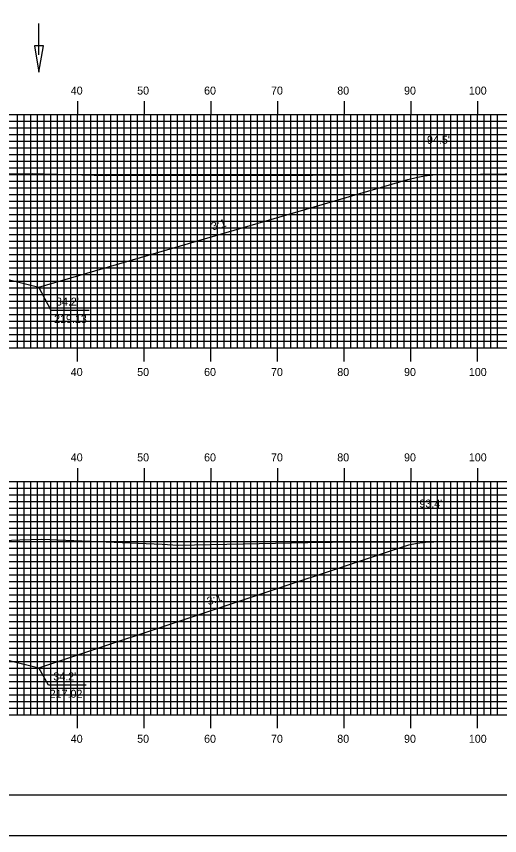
# Model space of a CAD drawing. Extents: x 1802323 to 1802666, y 442591 to 442811.
# Drawn here: x 1802519.4 to 1802591.9, y 442590.5 to 442713.4 of the extents above; entities that cross this region are included whole.
import ezdxf

# ---------------------------------------------------------------- set-up
doc = ezdxf.new("R2010")
doc.units = 0
for name, color, linetype in [('ANNOTATION', 7, 'Continuous'), ('BORDER', 7, 'Continuous'), ('D_Drainage_Ditch_Line', 7, 'Continuous'), ('D_Roadway_Centerline', 7, 'Continuous'), ('D_Roadway_SlopeLines', 7, 'Continuous'), ('D_Text_Standard', 7, 'Continuous'), ('H_V ANNOTATION', 7, 'Continuous'), ('MAJOR', 7, 'Continuous'), ('MINOR', 7, 'Continuous'), ('PLOT BOUNDARY', 7, 'Continuous'), ('S_Roadway_Centerline', 7, 'Continuous')]:
    doc.layers.add(name, color=color, linetype=linetype)

msp = doc.modelspace()

# ---------------------------------------------------------------- linework, layer by layer
at = {"layer": 'ANNOTATION'}
for points in [[(1802530.31, 442669.3), (1802524.62, 442669.3), (1802522.78, 442672.8)], [(1802529.9, 442613.09), (1802524.21, 442613.09), (1802522.78, 442615.69)]]:
    msp.add_lwpolyline(points, dxfattribs=at)
at = {"layer": 'BORDER'}
msp.add_lwpolyline([(1802339, 442596.67), (1802659, 442596.67), (1802659, 442806.67), (1802339, 442806.67)], close=True, dxfattribs=at)
at = {"layer": 'D_Drainage_Ditch_Line'}
msp.add_line((1802522.8, 442707.65), (1802522.8, 442712.35), dxfattribs=at)
msp.add_lwpolyline([(1802523.46, 442708.96), (1802522.15, 442708.96), (1802522.8, 442705.03)], close=True, dxfattribs=at)
at = {"layer": 'D_Roadway_Centerline'}
for points in [[(1802396.07, 442689.17), (1802397.32, 442689.09), (1802398.57, 442688.93), (1802399.82, 442688.68), (1802401.07, 442688.36), (1802454.43, 442672.8), (1802458.43, 442673.8), (1802468.6, 442676.34), (1802476.6, 442676.66), (1802488.6, 442676.9), (1802500.6, 442676.66), (1802508.6, 442676.34), (1802518.78, 442673.8), (1802522.78, 442672.8), (1802578.12, 442688.94), (1802579.37, 442689.26), (1802580.62, 442689.49), (1802581.87, 442689.62), (1802583.12, 442689.67)], [(1802397.15, 442633.97), (1802398.4, 442633.91), (1802399.65, 442633.74), (1802400.9, 442633.48), (1802402.15, 442633.11), (1802454.43, 442615.69), (1802458.43, 442616.69), (1802468.6, 442619.23), (1802476.6, 442619.55), (1802488.6, 442619.79), (1802500.6, 442619.55), (1802508.6, 442619.23), (1802518.78, 442616.69), (1802522.78, 442615.69), (1802577.02, 442633.77), (1802578.27, 442634.13), (1802579.52, 442634.39), (1802580.77, 442634.56), (1802582.02, 442634.61)]]:
    msp.add_lwpolyline(points, dxfattribs=at)
at = {"layer": 'D_Roadway_SlopeLines'}
for points in [[(1802522.78, 442672.8), (1802578.12, 442688.94), (1802579.37, 442689.26), (1802580.62, 442689.49), (1802581.87, 442689.62), (1802583.12, 442689.67)], [(1802508.6, 442676.34), (1802522.78, 442672.8)], [(1802522.78, 442615.69), (1802577.02, 442633.77), (1802578.27, 442634.13), (1802579.52, 442634.39), (1802580.77, 442634.56), (1802582.02, 442634.61)], [(1802508.6, 442619.23), (1802522.78, 442615.69)]]:
    msp.add_lwpolyline(points, dxfattribs=at)
at = {"layer": 'MAJOR'}
for p, q in [((1802528.6, 442700.67), (1802528.6, 442698.67)), ((1802538.6, 442700.67), (1802538.6, 442698.67)), ((1802548.6, 442700.67), (1802548.6, 442698.67)), ((1802558.6, 442700.67), (1802558.6, 442698.67)), ((1802568.6, 442700.67), (1802568.6, 442698.67)), ((1802578.6, 442700.67), (1802578.6, 442698.67)), ((1802588.6, 442700.67), (1802588.6, 442698.67)), ((1802348.6, 442698.67), (1802628.6, 442698.67)), ((1802348.6, 442698.67), (1802628.6, 442698.67)), ((1802528.6, 442663.67), (1802528.6, 442698.67)), ((1802538.6, 442663.67), (1802538.6, 442698.67)), ((1802548.6, 442663.67), (1802548.6, 442698.67)), ((1802558.6, 442663.67), (1802558.6, 442698.67)), ((1802568.6, 442663.67), (1802568.6, 442698.67)), ((1802578.6, 442663.67), (1802578.6, 442698.67)), ((1802588.6, 442663.67), (1802588.6, 442698.67)), ((1802348.6, 442693.67), (1802628.6, 442693.67)), ((1802348.6, 442688.67), (1802628.6, 442688.67)), ((1802348.6, 442683.67), (1802628.6, 442683.67)), ((1802348.6, 442678.67), (1802628.6, 442678.67)), ((1802348.6, 442673.67), (1802628.6, 442673.67)), ((1802348.6, 442668.67), (1802628.6, 442668.67)), ((1802348.6, 442663.67), (1802628.6, 442663.67)), ((1802348.6, 442663.67), (1802628.6, 442663.67)), ((1802528.6, 442661.66), (1802528.6, 442663.67)), ((1802538.6, 442661.66), (1802538.6, 442663.67)), ((1802548.6, 442661.66), (1802548.6, 442663.67)), ((1802558.6, 442661.66), (1802558.6, 442663.67)), ((1802568.6, 442661.66), (1802568.6, 442663.67)), ((1802578.6, 442661.66), (1802578.6, 442663.67)), ((1802588.6, 442661.66), (1802588.6, 442663.67)), ((1802528.6, 442645.67), (1802528.6, 442643.67)), ((1802538.6, 442645.67), (1802538.6, 442643.67)), ((1802548.6, 442645.67), (1802548.6, 442643.67)), ((1802558.6, 442645.67), (1802558.6, 442643.67)), ((1802568.6, 442645.67), (1802568.6, 442643.67)), ((1802578.6, 442645.67), (1802578.6, 442643.67)), ((1802588.6, 442645.67), (1802588.6, 442643.67)), ((1802348.6, 442643.67), (1802628.6, 442643.67)), ((1802348.6, 442643.67), (1802628.6, 442643.67)), ((1802528.6, 442608.67), (1802528.6, 442643.67)), ((1802538.6, 442608.67), (1802538.6, 442643.67)), ((1802548.6, 442608.67), (1802548.6, 442643.67)), ((1802558.6, 442608.67), (1802558.6, 442643.67)), ((1802568.6, 442608.67), (1802568.6, 442643.67)), ((1802578.6, 442608.67), (1802578.6, 442643.67)), ((1802588.6, 442608.67), (1802588.6, 442643.67)), ((1802348.6, 442638.67), (1802628.6, 442638.67)), ((1802348.6, 442633.67), (1802628.6, 442633.67)), ((1802348.6, 442628.67), (1802628.6, 442628.67)), ((1802348.6, 442623.67), (1802628.6, 442623.67)), ((1802348.6, 442618.67), (1802628.6, 442618.67)), ((1802348.6, 442613.67), (1802628.6, 442613.67)), ((1802348.6, 442608.67), (1802628.6, 442608.67)), ((1802348.6, 442608.67), (1802628.6, 442608.67)), ((1802528.6, 442606.66), (1802528.6, 442608.67)), ((1802538.6, 442606.66), (1802538.6, 442608.67)), ((1802548.6, 442606.66), (1802548.6, 442608.67)), ((1802558.6, 442606.66), (1802558.6, 442608.67)), ((1802568.6, 442606.66), (1802568.6, 442608.67)), ((1802578.6, 442606.66), (1802578.6, 442608.67)), ((1802588.6, 442606.66), (1802588.6, 442608.67))]:
    msp.add_line(p, q, dxfattribs=at)
at = {"layer": 'MINOR'}
for p, q in [((1802519.6, 442663.67), (1802519.6, 442698.67)), ((1802520.6, 442663.67), (1802520.6, 442698.67)), ((1802521.6, 442663.67), (1802521.6, 442698.67)), ((1802522.6, 442663.67), (1802522.6, 442698.67)), ((1802523.6, 442663.67), (1802523.6, 442698.67)), ((1802524.6, 442663.67), (1802524.6, 442698.67)), ((1802525.6, 442663.67), (1802525.6, 442698.67)), ((1802526.6, 442663.67), (1802526.6, 442698.67)), ((1802527.6, 442663.67), (1802527.6, 442698.67)), ((1802529.6, 442663.67), (1802529.6, 442698.67)), ((1802530.6, 442663.67), (1802530.6, 442698.67)), ((1802531.6, 442663.67), (1802531.6, 442698.67)), ((1802532.6, 442663.67), (1802532.6, 442698.67)), ((1802533.6, 442663.67), (1802533.6, 442698.67)), ((1802534.6, 442663.67), (1802534.6, 442698.67)), ((1802535.6, 442663.67), (1802535.6, 442698.67)), ((1802536.6, 442663.67), (1802536.6, 442698.67)), ((1802537.6, 442663.67), (1802537.6, 442698.67)), ((1802539.6, 442663.67), (1802539.6, 442698.67)), ((1802540.6, 442663.67), (1802540.6, 442698.67)), ((1802541.6, 442663.67), (1802541.6, 442698.67)), ((1802542.6, 442663.67), (1802542.6, 442698.67)), ((1802543.6, 442663.67), (1802543.6, 442698.67)), ((1802544.6, 442663.67), (1802544.6, 442698.67)), ((1802545.6, 442663.67), (1802545.6, 442698.67)), ((1802546.6, 442663.67), (1802546.6, 442698.67)), ((1802547.6, 442663.67), (1802547.6, 442698.67)), ((1802549.6, 442663.67), (1802549.6, 442698.67)), ((1802550.6, 442663.67), (1802550.6, 442698.67)), ((1802551.6, 442663.67), (1802551.6, 442698.67)), ((1802552.6, 442663.67), (1802552.6, 442698.67)), ((1802553.6, 442663.67), (1802553.6, 442698.67)), ((1802554.6, 442663.67), (1802554.6, 442698.67)), ((1802555.6, 442663.67), (1802555.6, 442698.67)), ((1802556.6, 442663.67), (1802556.6, 442698.67)), ((1802557.6, 442663.67), (1802557.6, 442698.67)), ((1802559.6, 442663.67), (1802559.6, 442698.67)), ((1802560.6, 442663.67), (1802560.6, 442698.67)), ((1802561.6, 442663.67), (1802561.6, 442698.67)), ((1802562.6, 442663.67), (1802562.6, 442698.67)), ((1802563.6, 442663.67), (1802563.6, 442698.67)), ((1802564.6, 442663.67), (1802564.6, 442698.67)), ((1802565.6, 442663.67), (1802565.6, 442698.67)), ((1802566.6, 442663.67), (1802566.6, 442698.67)), ((1802567.6, 442663.67), (1802567.6, 442698.67)), ((1802569.6, 442663.67), (1802569.6, 442698.67)), ((1802570.6, 442663.67), (1802570.6, 442698.67)), ((1802571.6, 442663.67), (1802571.6, 442698.67)), ((1802572.6, 442663.67), (1802572.6, 442698.67)), ((1802573.6, 442663.67), (1802573.6, 442698.67)), ((1802574.6, 442663.67), (1802574.6, 442698.67)), ((1802575.6, 442663.67), (1802575.6, 442698.67)), ((1802576.6, 442663.67), (1802576.6, 442698.67)), ((1802577.6, 442663.67), (1802577.6, 442698.67)), ((1802579.6, 442663.67), (1802579.6, 442698.67)), ((1802580.6, 442663.67), (1802580.6, 442698.67)), ((1802581.6, 442663.67), (1802581.6, 442698.67)), ((1802582.6, 442663.67), (1802582.6, 442698.67)), ((1802583.6, 442663.67), (1802583.6, 442698.67)), ((1802584.6, 442663.67), (1802584.6, 442698.67)), ((1802585.6, 442663.67), (1802585.6, 442698.67)), ((1802586.6, 442663.67), (1802586.6, 442698.67)), ((1802587.6, 442663.67), (1802587.6, 442698.67)), ((1802589.6, 442663.67), (1802589.6, 442698.67)), ((1802590.6, 442663.67), (1802590.6, 442698.67)), ((1802591.6, 442663.67), (1802591.6, 442698.67)), ((1802348.6, 442697.67), (1802628.6, 442697.67)), ((1802348.6, 442696.67), (1802628.6, 442696.67)), ((1802348.6, 442695.67), (1802628.6, 442695.67)), ((1802348.6, 442694.67), (1802628.6, 442694.67)), ((1802348.6, 442692.67), (1802628.6, 442692.67)), ((1802348.6, 442691.67), (1802628.6, 442691.67)), ((1802348.6, 442690.67), (1802628.6, 442690.67)), ((1802348.6, 442689.67), (1802628.6, 442689.67)), ((1802348.6, 442687.67), (1802628.6, 442687.67)), ((1802348.6, 442686.67), (1802628.6, 442686.67)), ((1802348.6, 442685.67), (1802628.6, 442685.67)), ((1802348.6, 442684.67), (1802628.6, 442684.67)), ((1802348.6, 442682.67), (1802628.6, 442682.67)), ((1802348.6, 442681.67), (1802628.6, 442681.67)), ((1802348.6, 442680.67), (1802628.6, 442680.67)), ((1802348.6, 442679.67), (1802628.6, 442679.67)), ((1802348.6, 442677.67), (1802628.6, 442677.67)), ((1802348.6, 442676.67), (1802628.6, 442676.67)), ((1802348.6, 442675.67), (1802628.6, 442675.67)), ((1802348.6, 442674.67), (1802628.6, 442674.67)), ((1802348.6, 442672.67), (1802628.6, 442672.67)), ((1802348.6, 442671.67), (1802628.6, 442671.67)), ((1802348.6, 442670.67), (1802628.6, 442670.67)), ((1802348.6, 442669.67), (1802628.6, 442669.67)), ((1802348.6, 442667.67), (1802628.6, 442667.67)), ((1802348.6, 442666.67), (1802628.6, 442666.67)), ((1802348.6, 442665.67), (1802628.6, 442665.67)), ((1802348.6, 442664.67), (1802628.6, 442664.67)), ((1802519.6, 442608.67), (1802519.6, 442643.67)), ((1802520.6, 442608.67), (1802520.6, 442643.67)), ((1802521.6, 442608.67), (1802521.6, 442643.67)), ((1802522.6, 442608.67), (1802522.6, 442643.67)), ((1802523.6, 442608.67), (1802523.6, 442643.67)), ((1802524.6, 442608.67), (1802524.6, 442643.67)), ((1802525.6, 442608.67), (1802525.6, 442643.67)), ((1802526.6, 442608.67), (1802526.6, 442643.67)), ((1802527.6, 442608.67), (1802527.6, 442643.67)), ((1802529.6, 442608.67), (1802529.6, 442643.67)), ((1802530.6, 442608.67), (1802530.6, 442643.67)), ((1802531.6, 442608.67), (1802531.6, 442643.67)), ((1802532.6, 442608.67), (1802532.6, 442643.67)), ((1802533.6, 442608.67), (1802533.6, 442643.67)), ((1802534.6, 442608.67), (1802534.6, 442643.67)), ((1802535.6, 442608.67), (1802535.6, 442643.67)), ((1802536.6, 442608.67), (1802536.6, 442643.67)), ((1802537.6, 442608.67), (1802537.6, 442643.67)), ((1802539.6, 442608.67), (1802539.6, 442643.67)), ((1802540.6, 442608.67), (1802540.6, 442643.67)), ((1802541.6, 442608.67), (1802541.6, 442643.67)), ((1802542.6, 442608.67), (1802542.6, 442643.67)), ((1802543.6, 442608.67), (1802543.6, 442643.67)), ((1802544.6, 442608.67), (1802544.6, 442643.67)), ((1802545.6, 442608.67), (1802545.6, 442643.67)), ((1802546.6, 442608.67), (1802546.6, 442643.67)), ((1802547.6, 442608.67), (1802547.6, 442643.67)), ((1802549.6, 442608.67), (1802549.6, 442643.67)), ((1802550.6, 442608.67), (1802550.6, 442643.67)), ((1802551.6, 442608.67), (1802551.6, 442643.67)), ((1802552.6, 442608.67), (1802552.6, 442643.67)), ((1802553.6, 442608.67), (1802553.6, 442643.67)), ((1802554.6, 442608.67), (1802554.6, 442643.67)), ((1802555.6, 442608.67), (1802555.6, 442643.67)), ((1802556.6, 442608.67), (1802556.6, 442643.67)), ((1802557.6, 442608.67), (1802557.6, 442643.67)), ((1802559.6, 442608.67), (1802559.6, 442643.67)), ((1802560.6, 442608.67), (1802560.6, 442643.67)), ((1802561.6, 442608.67), (1802561.6, 442643.67)), ((1802562.6, 442608.67), (1802562.6, 442643.67)), ((1802563.6, 442608.67), (1802563.6, 442643.67)), ((1802564.6, 442608.67), (1802564.6, 442643.67)), ((1802565.6, 442608.67), (1802565.6, 442643.67)), ((1802566.6, 442608.67), (1802566.6, 442643.67)), ((1802567.6, 442608.67), (1802567.6, 442643.67)), ((1802569.6, 442608.67), (1802569.6, 442643.67)), ((1802570.6, 442608.67), (1802570.6, 442643.67)), ((1802571.6, 442608.67), (1802571.6, 442643.67)), ((1802572.6, 442608.67), (1802572.6, 442643.67)), ((1802573.6, 442608.67), (1802573.6, 442643.67)), ((1802574.6, 442608.67), (1802574.6, 442643.67)), ((1802575.6, 442608.67), (1802575.6, 442643.67)), ((1802576.6, 442608.67), (1802576.6, 442643.67)), ((1802577.6, 442608.67), (1802577.6, 442643.67)), ((1802579.6, 442608.67), (1802579.6, 442643.67)), ((1802580.6, 442608.67), (1802580.6, 442643.67)), ((1802581.6, 442608.67), (1802581.6, 442643.67)), ((1802582.6, 442608.67), (1802582.6, 442643.67)), ((1802583.6, 442608.67), (1802583.6, 442643.67)), ((1802584.6, 442608.67), (1802584.6, 442643.67)), ((1802585.6, 442608.67), (1802585.6, 442643.67)), ((1802586.6, 442608.67), (1802586.6, 442643.67)), ((1802587.6, 442608.67), (1802587.6, 442643.67)), ((1802589.6, 442608.67), (1802589.6, 442643.67)), ((1802590.6, 442608.67), (1802590.6, 442643.67)), ((1802591.6, 442608.67), (1802591.6, 442643.67)), ((1802348.6, 442642.67), (1802628.6, 442642.67)), ((1802348.6, 442641.67), (1802628.6, 442641.67)), ((1802348.6, 442640.67), (1802628.6, 442640.67)), ((1802348.6, 442639.67), (1802628.6, 442639.67)), ((1802348.6, 442637.67), (1802628.6, 442637.67)), ((1802348.6, 442636.67), (1802628.6, 442636.67)), ((1802348.6, 442635.67), (1802628.6, 442635.67)), ((1802348.6, 442634.67), (1802628.6, 442634.67)), ((1802348.6, 442632.67), (1802628.6, 442632.67)), ((1802348.6, 442631.67), (1802628.6, 442631.67)), ((1802348.6, 442630.67), (1802628.6, 442630.67)), ((1802348.6, 442629.67), (1802628.6, 442629.67)), ((1802348.6, 442627.67), (1802628.6, 442627.67)), ((1802348.6, 442626.67), (1802628.6, 442626.67)), ((1802348.6, 442625.67), (1802628.6, 442625.67)), ((1802348.6, 442624.67), (1802628.6, 442624.67)), ((1802348.6, 442622.67), (1802628.6, 442622.67)), ((1802348.6, 442621.67), (1802628.6, 442621.67)), ((1802348.6, 442620.67), (1802628.6, 442620.67)), ((1802348.6, 442619.67), (1802628.6, 442619.67)), ((1802348.6, 442617.67), (1802628.6, 442617.67)), ((1802348.6, 442616.67), (1802628.6, 442616.67)), ((1802348.6, 442615.67), (1802628.6, 442615.67)), ((1802348.6, 442614.67), (1802628.6, 442614.67)), ((1802348.6, 442612.67), (1802628.6, 442612.67)), ((1802348.6, 442611.67), (1802628.6, 442611.67)), ((1802348.6, 442610.67), (1802628.6, 442610.67)), ((1802348.6, 442609.67), (1802628.6, 442609.67))]:
    msp.add_line(p, q, dxfattribs=at)
at = {"layer": 'PLOT BOUNDARY'}
msp.add_lwpolyline([(1802322.81, 442590.55), (1802662.81, 442590.55), (1802662.81, 442810.55), (1802322.81, 442810.55)], close=True, dxfattribs=at)
at = {"layer": 'S_Roadway_Centerline'}
for points in [[(1802507.23, 442689.68), (1802521.77, 442689.85), (1802532.92, 442689.56), (1802542.65, 442689.58), (1802558.19, 442689.59), (1802561.43, 442689.59), (1802563.86, 442689.58), (1802573.13, 442689.67), (1802584.23, 442689.67), (1802585.29, 442689.69), (1802596.5, 442689.86), (1802606.34, 442689.81), (1802608.02, 442689.8), (1802610.12, 442689.78), (1802619.94, 442689.88), (1802628.21, 442689.81), (1802628.6, 442689.81)], [(1802516.07, 442634.75), (1802519.95, 442634.88), (1802523.24, 442635.01), (1802541.26, 442634.25), (1802543.67, 442634.08), (1802558.29, 442634.4), (1802565.52, 442634.56), (1802566.08, 442634.55), (1802566.8, 442634.53), (1802586.57, 442634.64), (1802588.92, 442634.72), (1802592.53, 442634.68), (1802601.35, 442634.81), (1802607.76, 442634.75), (1802618.96, 442634.77), (1802628.6, 442634.72)]]:
    msp.add_lwpolyline(points, dxfattribs=at)

# ---------------------------------------------------------------- texts
at = {"layer": 'ANNOTATION'}
for rotation, p in [(16.2602, (1802548.85, 442681.29)), (18.4349, (1802548.24, 442625.08))]:
    msp.add_text('3:1', height=1.2, rotation=rotation, dxfattribs=at).set_placement(p)
for s, p in [("34.2'", (1802525.35, 442670.03)), ('219.13', (1802525.07, 442667.43)), ("34.2'", (1802524.95, 442613.82)), ('217.02', (1802524.41, 442611.22))]:
    msp.add_text(s, height=1.2, dxfattribs=at).set_placement(p)
at = {"layer": 'D_Text_Standard'}
for s, p in [("94.5'", (1802581.01, 442694.29)), ("93.4'", (1802579.87, 442639.74))]:
    msp.add_text(s, height=1.2, dxfattribs=at).set_placement(p)
at = {"layer": 'H_V ANNOTATION'}
for s, p in [('40', (1802527.57, 442701.67)), ('50', (1802537.53, 442701.67)), ('60', (1802547.57, 442701.67)), ('70', (1802557.61, 442701.67)), ('80', (1802567.55, 442701.67)), ('90', (1802577.57, 442701.67)), ('100', (1802587.29, 442701.67)), ('40', (1802527.57, 442659.47)), ('50', (1802537.53, 442659.47)), ('60', (1802547.57, 442659.47)), ('70', (1802557.61, 442659.47)), ('80', (1802567.55, 442659.47)), ('90', (1802577.57, 442659.47)), ('100', (1802587.29, 442659.47)), ('40', (1802527.57, 442646.67)), ('50', (1802537.53, 442646.67)), ('60', (1802547.57, 442646.67)), ('70', (1802557.61, 442646.67)), ('80', (1802567.55, 442646.67)), ('90', (1802577.57, 442646.67)), ('100', (1802587.29, 442646.67)), ('40', (1802527.57, 442604.47)), ('50', (1802537.53, 442604.47)), ('60', (1802547.57, 442604.47)), ('70', (1802557.61, 442604.47)), ('80', (1802567.55, 442604.47)), ('90', (1802577.57, 442604.47)), ('100', (1802587.29, 442604.47))]:
    msp.add_text(s, height=1.2, dxfattribs=at).set_placement(p)

doc.saveas('drawing.dxf')
